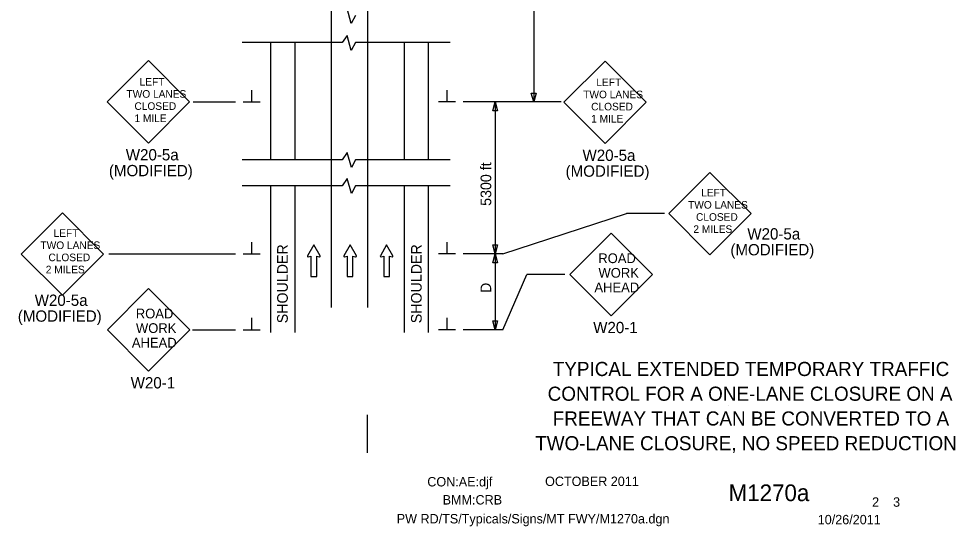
# Model space of a CAD drawing. Extents: x 16794 to 19504, y 7009 to 8243.
# Drawn here: x 17851 to 18468, y 7218 to 7552 of the extents above; entities that cross this region are included whole.
import ezdxf

# ---------------------------------------------------------------- set-up
doc = ezdxf.new("R2010")
doc.units = 0
for name, color, linetype in [('ALI_LEGAL_EX', 7, 'Continuous'), ('BORDER', 7, 'Continuous'), ('BORDER_SIGNAL_WO', 7, 'Continuous'), ('MT_SCRATCH_LEVEL_E', 7, 'Continuous'), ('PAVT_EDGE_EX', 7, 'Continuous'), ('TRAFFIC_SIGNS_PR', 7, 'Continuous'), ('TYPICAL_TEXT_DIMEN_PR', 7, 'Continuous')]:
    doc.layers.add(name, color=color, linetype=linetype)

msp = doc.modelspace()

# ---------------------------------------------------------------- linework, layer by layer
at = {"layer": 'ALI_LEGAL_EX'}
for p, q in [((18056.37, 8191.42), (18056.37, 7362.23)), ((18080.37, 8191.42), (18080.37, 7362.23)), ((18080.37, 8191.42), (18080.37, 7362.23))]:
    msp.add_line(p, q, dxfattribs=at)
for points in [[(18056.37, 7491.42), (18056.37, 7466.42)], [(18080.37, 7491.42), (18080.37, 7466.42)], [(18056.37, 7391.42), (18056.37, 7366.42)], [(18080.37, 7391.42), (18080.37, 7366.42)], [(18080.37, 7266.42), (18080.37, 7291.42)]]:
    msp.add_lwpolyline(points, dxfattribs=at)
at = {"layer": 'BORDER'}
msp.add_line((18318.25, 7297.5), (18318.25, 7297.5), dxfattribs=at)
at = {"layer": 'MT_SCRATCH_LEVEL_E'}
for p, q in [((18044.92, 7403.49), (18040.81, 7396.25)), ((18049.07, 7396.25), (18044.92, 7403.49)), ((18068.83, 7403.49), (18064.72, 7396.25)), ((18072.97, 7396.25), (18068.83, 7403.49)), ((18092.88, 7403.49), (18088.77, 7396.25)), ((18097.03, 7396.25), (18092.88, 7403.49)), ((18041.29, 7395.56), (18043.07, 7395.88)), ((18043.07, 7395.88), (18043.07, 7382.62)), ((18046.81, 7382.62), (18046.81, 7395.88)), ((18046.81, 7395.88), (18048.59, 7395.56)), ((18065.2, 7395.56), (18066.97, 7395.88)), ((18066.97, 7395.88), (18066.97, 7382.62)), ((18070.72, 7382.62), (18070.72, 7395.88)), ((18070.72, 7395.88), (18072.49, 7395.56)), ((18089.25, 7395.56), (18091.03, 7395.88)), ((18091.03, 7395.88), (18091.03, 7382.62)), ((18094.77, 7382.62), (18094.77, 7395.88)), ((18094.77, 7395.88), (18096.55, 7395.56)), ((18043.07, 7382.62), (18046.81, 7382.62)), ((18066.97, 7382.62), (18070.72, 7382.62)), ((18091.03, 7382.62), (18094.77, 7382.62))]:
    msp.add_line(p, q, dxfattribs=at)
for centre, start, end in [((18041.22, 7396.02), 150.42484, 279.96381), ((18048.66, 7396.02), 260.03619, 29.77312), ((18065.12, 7396.02), 150.42484, 279.96381), ((18072.56, 7396.02), 260.03619, 29.77312), ((18089.18, 7396.02), 150.42484, 279.96381), ((18096.62, 7396.02), 260.03619, 29.77312)]:
    msp.add_arc(centre, 0.463, start, end, dxfattribs=at)
at = {"layer": 'PAVT_EDGE_EX'}
for p, q in [((18016.37, 7536.58), (18016.37, 7459.44)), ((18032.37, 7536.58), (18032.37, 7459.44)), ((18104.37, 7536.6), (18104.37, 7459.44)), ((18120.37, 7536.6), (18120.37, 7459.44)), ((18016.37, 7442.3), (18016.37, 7345.73)), ((18032.37, 7442.3), (18032.37, 7345.73)), ((18104.37, 7442.3), (18104.37, 7345.73)), ((18120.37, 7442.3), (18120.37, 7345.73))]:
    msp.add_line(p, q, dxfattribs=at)
at = {"layer": 'TRAFFIC_SIGNS_PR'}
for p, q in [((17935.92, 7524.77), (17908.77, 7497.62)), ((17963.08, 7497.62), (17935.92, 7524.77)), ((18236.83, 7524.44), (18209.67, 7497.29)), ((18263.98, 7497.29), (18236.83, 7524.44)), ((17908.77, 7497.62), (17935.92, 7470.47)), ((17935.92, 7470.47), (17963.08, 7497.62)), ((18209.67, 7497.29), (18236.83, 7470.14)), ((18236.83, 7470.14), (18263.98, 7497.29)), ((18305.91, 7451.12), (18278.76, 7423.97)), ((18333.07, 7423.97), (18305.91, 7451.12)), ((17879.25, 7424.52), (17852.1, 7397.36)), ((17906.41, 7397.36), (17879.25, 7424.52)), ((18278.76, 7423.97), (18305.91, 7396.82)), ((18305.91, 7396.82), (18333.07, 7423.97)), ((18240.83, 7411.01), (18213.68, 7383.86)), ((18267.98, 7383.86), (18240.83, 7411.01)), ((17852.1, 7397.36), (17879.25, 7370.21)), ((17879.25, 7370.21), (17906.41, 7397.36)), ((18213.68, 7383.86), (18240.83, 7356.71)), ((18240.83, 7356.71), (18267.98, 7383.86)), ((17936.1, 7374.61), (17908.95, 7347.46)), ((17963.26, 7347.46), (17936.1, 7374.61)), ((17908.95, 7347.46), (17936.1, 7320.3)), ((17936.1, 7320.3), (17963.26, 7347.46))]:
    msp.add_line(p, q, dxfattribs=at)
at = {"layer": 'TYPICAL_TEXT_DIMEN_PR'}
for p, q in [((18189.8, 7847.49), (18189.8, 7497.49)), ((18069.62, 7549.2), (18066.88, 7559.14)), ((18072.36, 7554.34), (18069.62, 7549.2)), ((18066.88, 7541.38), (18063.62, 7536.58)), ((18069.62, 7531.44), (18066.88, 7541.38)), ((18063.62, 7536.58), (17997.68, 7536.58)), ((18072.36, 7536.58), (18069.62, 7531.44)), ((18134.69, 7536.58), (18072.36, 7536.58)), ((18003.99, 7497.49), (18003.99, 7505.27)), ((18132.74, 7497.49), (18132.74, 7505.27)), ((18189.8, 7497.49), (18188.23, 7503.35)), ((18188.23, 7503.35), (18189.8, 7503.35)), ((18189.8, 7503.35), (18191.37, 7503.35)), ((18191.37, 7503.35), (18189.8, 7497.49)), ((17965.44, 7497.49), (17993.37, 7497.49)), ((17998.37, 7497.49), (18009.62, 7497.49)), ((18138.37, 7497.49), (18127.12, 7497.49)), ((18207.8, 7497.49), (18143.37, 7497.49)), ((18162.79, 7491.63), (18164.37, 7497.49)), ((18164.37, 7497.49), (18164.37, 7397.49)), ((18164.37, 7497.49), (18165.94, 7491.63)), ((18164.37, 7491.63), (18162.79, 7491.63)), ((18165.94, 7491.63), (18164.37, 7491.63)), ((18066.97, 7464.23), (18063.71, 7459.43)), ((18069.71, 7454.29), (18066.97, 7464.23)), ((18063.71, 7459.43), (17997.77, 7459.43)), ((18072.45, 7459.43), (18069.71, 7454.29)), ((18134.78, 7459.43), (18072.45, 7459.43)), ((18063.71, 7442.29), (17997.77, 7442.29)), ((18066.97, 7447.09), (18063.71, 7442.29)), ((18069.71, 7437.15), (18066.97, 7447.09)), ((18072.45, 7442.29), (18069.71, 7437.15)), ((18134.78, 7442.29), (18072.45, 7442.29)), ((18169.37, 7397.49), (18251.02, 7423.97)), ((18275.89, 7423.97), (18251.02, 7423.97)), ((18003.99, 7397.49), (18003.99, 7405.27)), ((18132.74, 7397.49), (18132.74, 7405.27)), ((18164.37, 7397.49), (18162.79, 7403.35)), ((18162.79, 7403.35), (18164.37, 7403.35)), ((18164.37, 7403.35), (18165.94, 7403.35)), ((18165.94, 7403.35), (18164.37, 7397.49)), ((17909.77, 7397.49), (17993.37, 7397.49)), ((17998.37, 7397.49), (18009.62, 7397.49)), ((18138.37, 7397.49), (18127.12, 7397.49)), ((18169.37, 7397.49), (18143.37, 7397.49)), ((18162.79, 7391.63), (18164.37, 7397.49)), ((18164.37, 7397.49), (18164.37, 7347.49)), ((18164.37, 7397.49), (18165.94, 7391.63)), ((18164.37, 7391.63), (18162.79, 7391.63)), ((18165.94, 7391.63), (18164.37, 7391.63)), ((18169.37, 7347.49), (18185.36, 7383.86)), ((18210.23, 7383.86), (18185.36, 7383.86)), ((18003.99, 7347.49), (18003.99, 7355.27)), ((18132.74, 7347.49), (18132.74, 7355.27)), ((18164.37, 7347.49), (18162.79, 7353.35)), ((18162.79, 7353.35), (18164.37, 7353.35)), ((18164.37, 7353.35), (18165.94, 7353.35)), ((18165.94, 7353.35), (18164.37, 7347.49)), ((17965.08, 7347.49), (17993.37, 7347.49)), ((17998.37, 7347.49), (18009.62, 7347.49)), ((18138.37, 7347.49), (18127.12, 7347.49)), ((18169.37, 7347.49), (18143.37, 7347.49))]:
    msp.add_line(p, q, dxfattribs=at)

# ---------------------------------------------------------------- texts
at = {"layer": 'BORDER'}
for s, p in [('TYPICAL EXTENDED TEMPORARY TRAFFIC', (18202.38, 7317.03)), ('CONTROL FOR A ONE-LANE CLOSURE ON A', (18199, 7300.73)), ('FREEWAY THAT CAN BE CONVERTED TO A', (18202.33, 7284.43)), ('TWO-LANE CLOSURE, NO SPEED REDUCTION ', (18190.79, 7268.13))]:
    msp.add_text(s, height=9.3, dxfattribs=at).set_placement(p)
at = {"layer": 'BORDER_SIGNAL_WO'}
for s, height, p in [('CON:AE:djf  ', 6.2, (18119.69, 7244.31)), ('    OCTOBER 2011    ', 6.2, (18188.08, 7244.59)), ('    M1270a   ', 11, (18301.86, 7234.63)), ('BMM:CRB   ', 6.2, (18129.81, 7232.42)), (' 2    3 ', 6.2, (18410.45, 7230.95)), ('PW RD/TS/Typicals/Signs/MT FWY/M1270a.dgn      ', 6.2, (18099.55, 7219.96)), ('10/26/2011    ', 6.2, (18376.93, 7219.38))]:
    msp.add_text(s, height=height, dxfattribs=at).set_placement(p)
at = {"layer": 'TRAFFIC_SIGNS_PR'}
for s, height, p in [('LEFT', 5, (17930.17, 7508.29)), ('LEFT', 5, (18231.08, 7507.96)), ('TWO LANES', 5, (17921.53, 7500.29)), ('TWO LANES', 5, (18222.43, 7499.96)), ('CLOSED', 5, (17926.76, 7492.3)), ('CLOSED', 5, (18227.66, 7491.96)), ('1 MILE', 5, (17926.75, 7484.3)), ('1 MILE', 5, (18227.66, 7483.96)), ('W20-5a', 7.44, (17921.06, 7459.03)), ('W20-5a', 7.44, (18221.97, 7458.69)), ('(MODIFIED)', 7.44, (17909.92, 7448.59)), ('(MODIFIED)', 7.44, (18210.82, 7448.26)), ('LEFT', 5, (18300.16, 7435.26)), ('TWO LANES', 5, (18291.52, 7427.26)), ('CLOSED', 5, (18296.75, 7419.26)), ('LEFT', 5, (17873.5, 7408.65)), ('2 MILES', 5, (18295, 7411.26)), ('W20-5a', 7.44, (18330.55, 7406.93)), ('TWO LANES', 5, (17864.86, 7400.65)), ('(MODIFIED)', 7.44, (18319.4, 7396.49)), ('CLOSED', 5, (17870.09, 7392.65)), ('ROAD', 6.4, (18232.37, 7391.39)), ('2 MILES', 5, (17868.34, 7384.65)), ('WORK', 6.4, (18232.48, 7381.79)), ('AHEAD', 6.4, (18229.79, 7372.19)), ('W20-5a', 7.44, (17861.04, 7363.23)), ('ROAD', 6.4, (17927.65, 7354.99)), ('(MODIFIED)', 7.44, (17849.9, 7352.79)), ('WORK', 6.4, (17927.75, 7345.39)), ('W20-1', 7.44, (18229, 7345.27)), ('AHEAD', 6.4, (17925.06, 7335.79)), ('W20-1', 7.44, (17924.27, 7308.86))]:
    msp.add_text(s, height=height, dxfattribs=at).set_placement(p)
at = {"layer": 'TYPICAL_TEXT_DIMEN_PR'}
for s, p in [('5300 ft', (18161.81, 7429.09)), ('SHOULDER', (18027.78, 7351.77)), ('SHOULDER', (18115.98, 7351.77)), ('D', (18161.81, 7371.71))]:
    msp.add_text(s, height=7, rotation=90, dxfattribs=at).set_placement(p)

doc.saveas('drawing.dxf')
